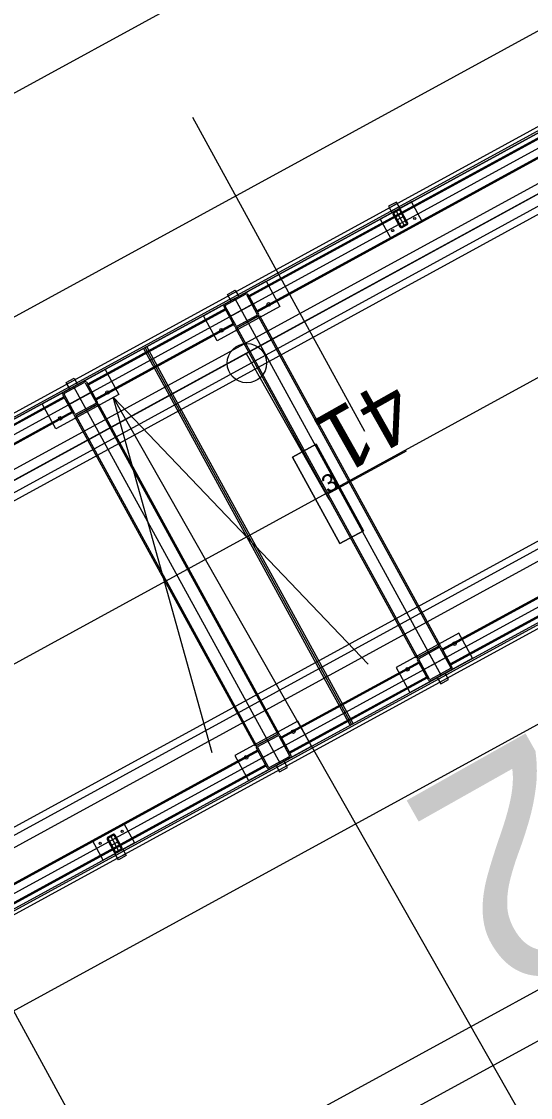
# Model space of a CAD drawing. Extents: x -783978 to -783565, y -1064821 to -1064596.
# Drawn here: x -783770.68 to -783767.84, y -1064687.65 to -1064681.64 of the extents above; entities that cross this region are included whole.
import ezdxf

# ---------------------------------------------------------------- set-up
doc = ezdxf.new("R2010")
doc.units = 0
for name, color, linetype in [('Default', 7, 'Continuous'), ('SO 01_11_01', 7, 'Continuous'), ('SO 01_20_01', 7, 'Continuous'), ('SO 01_50_01', 7, 'Continuous'), ('SO 01_74_01', 7, 'Continuous'), ('SO 01_86_02', 7, 'Continuous'), ('SO 01_86_04', 7, 'Continuous')]:
    doc.layers.add(name, color=color, linetype=linetype)

# ---------------------------------------------------------------- blocks, each defined once
blk = doc.blocks.new('POINT_DISPLAY')
at = {"layer": 'Default'}
blk.add_line((0, 0), (0, 0), dxfattribs=at)

msp = doc.modelspace()

# ---------------------------------------------------------------- linework, layer by layer
at = {"layer": 'SO 01_11_01'}
for p, q in [((-783772.8819, -1064683.2217), (-783730.898, -1064660.279)), ((-783768.6111, -1064691.0302), (-783772.8819, -1064683.2217)), ((-783767.2032, -1064688.9576), (-783770.1671, -1064683.7408))]:
    msp.add_line(p, q, dxfattribs=at)
msp.add_lwpolyline([(-783769.6139, -1064685.7267), (-783770.1671, -1064683.7408), (-783768.7444, -1064685.2327)], dxfattribs=at)
at = {"layer": 'SO 01_20_01'}
for p, q in [((-783735.0054, -1064663.7532), (-783787.4671, -1064692.4555)), ((-783735.2041, -1064664.4318), (-783786.7885, -1064692.6541)), ((-783786.6445, -1064692.9173), (-783735.3233, -1064664.839)), ((-783738.0171, -1064666.3812), (-783786.4402, -1064692.874)), ((-783786.421, -1064692.9091), (-783737.9979, -1064666.4163)), ((-783737.8741, -1064667.2605), (-783785.3352, -1064693.2269)), ((-783737.0912, -1064667.858), (-783785.7805, -1064694.4964)), ((-783785.6531, -1064694.3127), (-783737.23, -1064667.82)), ((-783737.2108, -1064667.855), (-783785.6339, -1064694.3478)), ((-783785.6366, -1064694.7596), (-783736.9472, -1064668.1212)), ((-783746.2961, -1064673.8055), (-783785.8354, -1064695.4379)), ((-783769.8533, -1064683.7307), (-783769.9973, -1064683.4675)), ((-783768.8366, -1064685.5682), (-783769.9885, -1064683.4627)), ((-783769.8357, -1064683.7211), (-783769.9797, -1064683.4579)), ((-783768.9893, -1064685.3098), (-783769.8533, -1064683.7307)), ((-783768.9718, -1064685.3002), (-783769.8357, -1064683.7211)), ((-783768.8453, -1064685.573), (-783768.9893, -1064685.3098)), ((-783768.8278, -1064685.5634), (-783768.9718, -1064685.3002))]:
    msp.add_line(p, q, dxfattribs=at)
at = {"layer": 'SO 01_50_01'}
for p, q in [((-783786.7885, -1064692.6541), (-783725.4827, -1064659.1131)), ((-783769.2428, -1064683.0547), (-783764.8564, -1064680.6549)), ((-783769.2427, -1064683.0548), (-783764.8563, -1064680.655)), ((-783769.2427, -1064683.0548), (-783764.8563, -1064680.655)), ((-783768.7628, -1064683.932), (-783769.7228, -1064682.1774)), ((-783773.6292, -1064685.4546), (-783769.2428, -1064683.0547)), ((-783773.6292, -1064685.4547), (-783769.2427, -1064683.0548)), ((-783773.6292, -1064685.4547), (-783769.2427, -1064683.0548))]:
    msp.add_line(p, q, dxfattribs=at)
for points in [[(-783784.7751, -1064696.3401), (-783745.2333, -1064674.7064)], [(-783784.6553, -1064696.5595), (-783745.1133, -1064674.9257)]]:
    msp.add_lwpolyline(points, dxfattribs=at)
at = {"layer": 'SO 01_74_01'}
for p, q in [((-783735.2185, -1064664.4055), (-783786.6099, -1064692.5222)), ((-783786.6003, -1064692.5398), (-783735.2089, -1064664.423)), ((-783785.4388, -1064694.6628), (-783745.8293, -1064672.9921)), ((-783745.8197, -1064673.0096), (-783785.4292, -1064694.6803)), ((-783766.8446, -1064681.7711), (-783769.4106, -1064683.175)), ((-783766.8416, -1064681.7767), (-783769.4076, -1064683.1806)), ((-783769.3657, -1064683.2572), (-783766.7996, -1064681.8533)), ((-783769.3626, -1064683.2628), (-783766.7966, -1064681.8589)), ((-783768.5865, -1064682.6501), (-783768.6304, -1064682.6741)), ((-783768.5673, -1064682.6851), (-783768.5865, -1064682.6501)), ((-783768.6304, -1064682.6741), (-783768.6112, -1064682.7091)), ((-783768.5817, -1064682.6588), (-783768.6256, -1064682.6828)), ((-783768.6256, -1064682.6828), (-783768.616, -1064682.7004)), ((-783768.616, -1064682.7004), (-783768.5721, -1064682.6764)), ((-783768.6112, -1064682.7091), (-783768.5673, -1064682.6851)), ((-783768.5721, -1064682.6764), (-783768.5817, -1064682.6588)), ((-783769.5296, -1064683.166), (-783769.4857, -1064683.142)), ((-783769.5104, -1064683.2011), (-783769.5296, -1064683.166)), ((-783769.4665, -1064683.1771), (-783769.5104, -1064683.2011)), ((-783769.4857, -1064683.142), (-783769.4665, -1064683.1771)), ((-783769.4106, -1064683.175), (-783769.3626, -1064683.2628)), ((-783769.4076, -1064683.1806), (-783769.3657, -1064683.2572)), ((-783769.5422, -1064683.247), (-783770.3099, -1064683.667)), ((-783769.5392, -1064683.2526), (-783770.3068, -1064683.6725)), ((-783769.4942, -1064683.3348), (-783769.5422, -1064683.247)), ((-783769.4973, -1064683.3292), (-783769.5392, -1064683.2526)), ((-783769.4822, -1064683.3567), (-783769.3506, -1064683.2847)), ((-783769.4752, -1064683.3529), (-783769.3577, -1064683.2885)), ((-783769.3577, -1064683.2885), (-783768.3497, -1064685.1308)), ((-783769.3506, -1064683.2847), (-783768.3427, -1064685.127)), ((-783770.2649, -1064683.7492), (-783769.4973, -1064683.3292)), ((-783770.2619, -1064683.7547), (-783769.4942, -1064683.3348)), ((-783768.4743, -1064685.199), (-783769.4822, -1064683.3567)), ((-783768.4673, -1064685.1952), (-783769.4752, -1064683.3529)), ((-783770.4288, -1064683.658), (-783770.3849, -1064683.634)), ((-783770.4096, -1064683.6931), (-783770.4288, -1064683.658)), ((-783770.3657, -1064683.6691), (-783770.4096, -1064683.6931)), ((-783770.3849, -1064683.634), (-783770.3657, -1064683.6691)), ((-783770.3099, -1064683.667), (-783770.2619, -1064683.7547)), ((-783770.3068, -1064683.6725), (-783770.2649, -1064683.7492)), ((-783770.4415, -1064683.739), (-783773.0075, -1064685.1429)), ((-783770.4384, -1064683.7445), (-783773.0045, -1064685.1485)), ((-783770.3935, -1064683.8267), (-783770.4415, -1064683.739)), ((-783770.3965, -1064683.8212), (-783770.4384, -1064683.7445)), ((-783770.3815, -1064683.8487), (-783770.2499, -1064683.7767)), ((-783770.3744, -1064683.8448), (-783770.2569, -1064683.7805)), ((-783770.2569, -1064683.7805), (-783769.2489, -1064685.6228)), ((-783770.2499, -1064683.7767), (-783769.2419, -1064685.619)), ((-783765.7646, -1064683.745), (-783768.3307, -1064685.1489)), ((-783765.7616, -1064683.7505), (-783768.3277, -1064685.1545)), ((-783772.9625, -1064685.2251), (-783770.3965, -1064683.8212)), ((-783772.9595, -1064685.2307), (-783770.3935, -1064683.8267)), ((-783769.3735, -1064685.691), (-783770.3815, -1064683.8487)), ((-783769.3665, -1064685.6871), (-783770.3744, -1064683.8448)), ((-783768.2857, -1064685.2311), (-783765.7197, -1064683.8272)), ((-783768.2827, -1064685.2367), (-783765.7167, -1064683.8328)), ((-783768.3427, -1064685.127), (-783768.4743, -1064685.199)), ((-783768.3497, -1064685.1308), (-783768.4673, -1064685.1952)), ((-783768.3307, -1064685.1489), (-783768.2827, -1064685.2367)), ((-783768.3277, -1064685.1545), (-783768.2857, -1064685.2311)), ((-783768.4623, -1064685.2209), (-783769.2299, -1064685.6409)), ((-783768.4593, -1064685.2265), (-783769.2269, -1064685.6464)), ((-783768.4143, -1064685.3087), (-783768.4623, -1064685.2209)), ((-783768.4173, -1064685.3031), (-783768.4593, -1064685.2265)), ((-783768.3146, -1064685.2826), (-783768.3584, -1064685.3066)), ((-783768.2954, -1064685.3177), (-783768.3146, -1064685.2826)), ((-783769.185, -1064685.7231), (-783768.4173, -1064685.3031)), ((-783769.1819, -1064685.7286), (-783768.4143, -1064685.3087)), ((-783768.3584, -1064685.3066), (-783768.3392, -1064685.3417)), ((-783768.3392, -1064685.3417), (-783768.2954, -1064685.3177)), ((-783769.2419, -1064685.619), (-783769.3735, -1064685.691)), ((-783769.2489, -1064685.6228), (-783769.3665, -1064685.6871)), ((-783769.2299, -1064685.6409), (-783769.1819, -1064685.7286)), ((-783769.2269, -1064685.6464), (-783769.185, -1064685.7231)), ((-783769.3615, -1064685.7129), (-783771.9276, -1064687.1168)), ((-783769.3585, -1064685.7184), (-783771.9245, -1064687.1223)), ((-783769.3135, -1064685.8006), (-783769.3615, -1064685.7129)), ((-783769.3165, -1064685.7951), (-783769.3585, -1064685.7184)), ((-783769.2138, -1064685.7746), (-783769.2577, -1064685.7986)), ((-783769.1946, -1064685.8097), (-783769.2138, -1064685.7746)), ((-783771.8826, -1064687.199), (-783769.3165, -1064685.7951)), ((-783771.8796, -1064687.2045), (-783769.3135, -1064685.8006)), ((-783769.2577, -1064685.7986), (-783769.2385, -1064685.8337)), ((-783769.2385, -1064685.8337), (-783769.1946, -1064685.8097)), ((-783770.1569, -1064686.2905), (-783770.113, -1064686.2665)), ((-783770.1377, -1064686.3256), (-783770.1569, -1064686.2905)), ((-783770.1521, -1064686.2993), (-783770.1082, -1064686.2753)), ((-783770.1425, -1064686.3169), (-783770.1521, -1064686.2993)), ((-783770.0986, -1064686.2929), (-783770.1425, -1064686.3169)), ((-783770.0938, -1064686.3016), (-783770.1377, -1064686.3256)), ((-783770.113, -1064686.2665), (-783770.0938, -1064686.3016)), ((-783770.1082, -1064686.2753), (-783770.0986, -1064686.2929))]:
    msp.add_line(p, q, dxfattribs=at)
for points in [[(-783735.1681, -1064664.4976), (-783787.4762, -1064693.1159)], [(-783734.0882, -1064666.4715), (-783786.3963, -1064695.0898)], [(-783768.5756, -1064682.6897), (-783768.6029, -1064682.7046)], [(-783768.5726, -1064682.6952), (-783768.5998, -1064682.7101)], [(-783768.5892, -1064682.6971), (-783768.5412, -1064682.7849)], [(-783768.5294, -1064682.7676), (-783768.5683, -1064682.6965)], [(-783768.5238, -1064682.7646), (-783768.5628, -1064682.6934)], [(-783768.6066, -1064682.7174), (-783768.5677, -1064682.7886)], [(-783768.6011, -1064682.7144), (-783768.5622, -1064682.7856)], [(-783768.5433, -1064682.729), (-783768.5872, -1064682.753)], [(-783768.5579, -1064682.7868), (-783768.5306, -1064682.7719)], [(-783768.5549, -1064682.7923), (-783768.5276, -1064682.7774)], [(-783769.5437, -1064683.2194), (-783769.4332, -1064683.1589)], [(-783769.5399, -1064683.2264), (-783769.4293, -1064683.1659)], [(-783769.4884, -1064683.1891), (-783768.3365, -1064685.2946)], [(-783769.4884, -1064683.1891), (-783769.4164, -1064683.3207)], [(-783769.4239, -1064683.1675), (-783769.3634, -1064683.278)], [(-783769.4169, -1064683.1636), (-783769.3564, -1064683.2742)], [(-783769.488, -1064683.3462), (-783769.5485, -1064683.2356)], [(-783769.481, -1064683.3423), (-783769.5415, -1064683.2318)], [(-783769.3866, -1064683.2189), (-783769.5182, -1064683.2909)], [(-783769.365, -1064683.2834), (-783769.4755, -1064683.3439)], [(-783769.3612, -1064683.2905), (-783769.4717, -1064683.3509)], [(-783770.4429, -1064683.7113), (-783770.3324, -1064683.6508)], [(-783770.4391, -1064683.7183), (-783770.3285, -1064683.6579)], [(-783770.3231, -1064683.6595), (-783770.2626, -1064683.77)], [(-783770.3161, -1064683.6556), (-783770.2556, -1064683.7662)], [(-783770.3872, -1064683.8381), (-783770.4477, -1064683.7276)], [(-783770.3802, -1064683.8343), (-783770.4407, -1064683.7238)], [(-783770.2859, -1064683.7109), (-783770.4175, -1064683.7829)], [(-783770.3877, -1064683.6811), (-783769.2357, -1064685.7866)], [(-783770.3877, -1064683.6811), (-783770.3157, -1064683.8127)], [(-783770.2642, -1064683.7754), (-783770.3748, -1064683.8359)], [(-783770.2604, -1064683.7824), (-783770.3709, -1064683.8429)], [(-783768.4638, -1064685.1932), (-783768.3532, -1064685.1328)], [(-783768.4599, -1064685.2003), (-783768.3494, -1064685.1398)], [(-783768.4085, -1064685.163), (-783768.3365, -1064685.2946)], [(-783768.344, -1064685.1414), (-783768.2835, -1064685.2519)], [(-783768.3369, -1064685.1375), (-783768.2765, -1064685.2481)], [(-783768.4081, -1064685.3201), (-783768.4685, -1064685.2095)], [(-783768.401, -1064685.3162), (-783768.4615, -1064685.2057)], [(-783768.3067, -1064685.1928), (-783768.4383, -1064685.2648)], [(-783768.2851, -1064685.2573), (-783768.3956, -1064685.3178)], [(-783768.2812, -1064685.2644), (-783768.3918, -1064685.3248)], [(-783769.363, -1064685.6852), (-783769.2525, -1064685.6247)], [(-783769.3591, -1064685.6922), (-783769.2486, -1064685.6318)], [(-783769.3077, -1064685.655), (-783769.2357, -1064685.7866)], [(-783769.2432, -1064685.6333), (-783769.1827, -1064685.7439)], [(-783769.2362, -1064685.6295), (-783769.1757, -1064685.74)], [(-783769.3073, -1064685.812), (-783769.3678, -1064685.7015)], [(-783769.3003, -1064685.8082), (-783769.3607, -1064685.6977)], [(-783769.2059, -1064685.6848), (-783769.3375, -1064685.7568)], [(-783769.1843, -1064685.7493), (-783769.2948, -1064685.8098)], [(-783769.1805, -1064685.7563), (-783769.291, -1064685.8168)], [(-783770.1693, -1064686.1833), (-783770.1966, -1064686.1983)], [(-783770.1663, -1064686.1889), (-783770.1936, -1064686.2038)], [(-783770.1829, -1064686.1908), (-783770.1349, -1064686.2785)], [(-783770.1231, -1064686.2613), (-783770.162, -1064686.1901)], [(-783770.1175, -1064686.2582), (-783770.1565, -1064686.1871)], [(-783770.2003, -1064686.2111), (-783770.1614, -1064686.2822)], [(-783770.1948, -1064686.2081), (-783770.1559, -1064686.2792)], [(-783770.137, -1064686.2227), (-783770.1809, -1064686.2467)], [(-783770.1516, -1064686.2805), (-783770.1243, -1064686.2655)], [(-783770.1486, -1064686.286), (-783770.1213, -1064686.2711)]]:
    msp.add_lwpolyline(points, dxfattribs=at)
for points in [[(-783768.5015, -1064682.6491), (-783768.6769, -1064682.7451), (-783768.6194, -1064682.8504), (-783768.4439, -1064682.7544)], [(-783769.2362, -1064683.2335), (-783769.5871, -1064683.4255), (-783769.6639, -1064683.2851), (-783769.313, -1064683.0931)], [(-783770.1354, -1064683.7255), (-783770.4863, -1064683.9174), (-783770.5631, -1064683.7771), (-783770.2122, -1064683.5851)], [(-783768.2378, -1064685.0582), (-783768.5888, -1064685.2502), (-783768.512, -1064685.3906), (-783768.161, -1064685.1986)], [(-783769.1371, -1064685.5502), (-783769.488, -1064685.7422), (-783769.4112, -1064685.8826), (-783769.0603, -1064685.6906)], [(-783770.0472, -1064686.2305), (-783770.2227, -1064686.3265), (-783770.2803, -1064686.2213), (-783770.1048, -1064686.1253)]]:
    msp.add_lwpolyline(points, close=True, dxfattribs=at)
for centre, radius in [((-783768.4846, -1064682.7425), 0.006), ((-783768.6074, -1064682.8097), 0.006), ((-783769.2992, -1064683.2224), 0.01), ((-783769.5624, -1064683.3664), 0.01), ((-783770.1985, -1064683.7144), 0.01), ((-783770.4616, -1064683.8584), 0.01), ((-783768.2625, -1064685.1173), 0.01), ((-783768.5257, -1064685.2613), 0.01), ((-783769.1617, -1064685.6093), 0.01), ((-783769.4249, -1064685.7533), 0.01), ((-783770.1167, -1064686.166), 0.006), ((-783770.2395, -1064686.2332), 0.006)]:
    msp.add_circle(centre, radius, dxfattribs=at)
for centre, radius, start, end in [((-783768.5983, -1064682.7129), 0.00945, 118.68349, 208.68349), ((-783768.5983, -1064682.7129), 0.00315, 118.68349, 208.68349), ((-783768.571, -1064682.698), 0.00945, 28.68349, 118.68349), ((-783768.571, -1064682.698), 0.00315, 28.68349, 118.68349), ((-783768.5321, -1064682.7691), 0.00315, 298.68349, 28.68349), ((-783768.5321, -1064682.7691), 0.00945, 298.68349, 28.68349), ((-783768.5594, -1064682.784), 0.00945, 208.68349, 298.68349), ((-783768.5594, -1064682.784), 0.00315, 208.68349, 298.68349), ((-783769.4274, -1064683.1694), 0.012, 28.68349, 118.68349), ((-783769.4274, -1064683.1694), 0.004, 28.68349, 118.68349), ((-783769.5379, -1064683.2299), 0.012, 118.68349, 208.68349), ((-783769.5379, -1064683.2299), 0.004, 118.68349, 208.68349), ((-783769.3669, -1064683.2799), 0.004, 298.68349, 28.68349), ((-783769.3669, -1064683.2799), 0.012, 298.68349, 28.68349), ((-783769.4775, -1064683.3404), 0.012, 208.68349, 298.68349), ((-783769.4775, -1064683.3404), 0.004, 208.68349, 298.68349), ((-783770.3266, -1064683.6614), 0.012, 28.68349, 118.68349), ((-783770.3266, -1064683.6614), 0.004, 28.68349, 118.68349), ((-783770.4372, -1064683.7218), 0.012, 118.68349, 208.68349), ((-783770.4372, -1064683.7218), 0.004, 118.68349, 208.68349), ((-783770.2661, -1064683.7719), 0.004, 298.68349, 28.68349), ((-783770.2661, -1064683.7719), 0.012, 298.68349, 28.68349), ((-783770.3767, -1064683.8324), 0.012, 208.68349, 298.68349), ((-783770.3767, -1064683.8324), 0.004, 208.68349, 298.68349), ((-783768.3475, -1064685.1433), 0.012, 28.68349, 118.68349), ((-783768.3475, -1064685.1433), 0.004, 28.68349, 118.68349), ((-783768.458, -1064685.2038), 0.012, 118.68349, 208.68349), ((-783768.458, -1064685.2038), 0.004, 118.68349, 208.68349), ((-783768.287, -1064685.2538), 0.004, 298.68349, 28.68349), ((-783768.287, -1064685.2538), 0.012, 298.68349, 28.68349), ((-783768.3975, -1064685.3143), 0.012, 208.68349, 298.68349), ((-783768.3975, -1064685.3143), 0.004, 208.68349, 298.68349), ((-783769.2467, -1064685.6353), 0.012, 28.68349, 118.68349), ((-783769.2467, -1064685.6353), 0.004, 28.68349, 118.68349), ((-783769.3572, -1064685.6957), 0.012, 118.68349, 208.68349), ((-783769.3572, -1064685.6957), 0.004, 118.68349, 208.68349), ((-783769.1862, -1064685.7458), 0.004, 298.68349, 28.68349), ((-783769.1862, -1064685.7458), 0.012, 298.68349, 28.68349), ((-783769.2968, -1064685.8063), 0.012, 208.68349, 298.68349), ((-783769.2968, -1064685.8063), 0.004, 208.68349, 298.68349), ((-783770.192, -1064686.2066), 0.00945, 118.68349, 208.68349), ((-783770.1648, -1064686.1916), 0.00945, 28.68349, 118.68349), ((-783770.1648, -1064686.1916), 0.00315, 28.68349, 118.68349), ((-783770.192, -1064686.2066), 0.00315, 118.68349, 208.68349), ((-783770.1258, -1064686.2628), 0.00945, 298.68349, 28.68349), ((-783770.1531, -1064686.2777), 0.00945, 208.68349, 298.68349), ((-783770.1531, -1064686.2777), 0.00315, 208.68349, 298.68349), ((-783770.1258, -1064686.2628), 0.00315, 298.68349, 28.68349)]:
    msp.add_arc(centre, radius, start, end, dxfattribs=at)
at = {"layer": 'SO 01_86_04'}
for p, q in [((-783769.4242, -1064683.4959), (-783768.9641, -1064684.3106)), ((-783769.0347, -1064684.0039), (-783769.1663, -1064684.0759)), ((-783769.0347, -1064684.0039), (-783769.1663, -1064684.0759)), ((-783769.1663, -1064684.0759), (-783769.0347, -1064684.0039)), ((-783769.1663, -1064684.0759), (-783769.0347, -1064684.0039)), ((-783768.7707, -1064684.4864), (-783769.0347, -1064684.0039)), ((-783768.7707, -1064684.4864), (-783769.0347, -1064684.0039)), ((-783769.0347, -1064684.0039), (-783768.7707, -1064684.4864)), ((-783769.0347, -1064684.0039), (-783768.7707, -1064684.4864)), ((-783769.1663, -1064684.0759), (-783768.9023, -1064684.5584)), ((-783769.1663, -1064684.0759), (-783768.9023, -1064684.5584)), ((-783768.9023, -1064684.5584), (-783769.1663, -1064684.0759)), ((-783768.9023, -1064684.5584), (-783769.1663, -1064684.0759)), ((-783768.9685, -1064684.2811), (-783768.5298, -1064684.0411)), ((-783768.9023, -1064684.5584), (-783768.7707, -1064684.4864)), ((-783768.9023, -1064684.5584), (-783768.7707, -1064684.4864)), ((-783768.7707, -1064684.4864), (-783768.9023, -1064684.5584)), ((-783768.7707, -1064684.4864), (-783768.9023, -1064684.5584))]:
    msp.add_line(p, q, dxfattribs=at)
for points in [[(-783738.3222, -1064666.4797), (-783740.5325, -1064667.689), (-783743.1715, -1064669.1328), (-783745.7538, -1064670.5456), (-783748.4385, -1064672.0145), (-783751.0413, -1064673.4385), (-783753.6847, -1064674.8847), (-783756.3281, -1064676.3309), (-783758.9715, -1064677.7772), (-783761.6149, -1064679.2234), (-783764.2583, -1064680.6696), (-783766.9018, -1064682.1159), (-783769.4633, -1064683.5173), (-783772.109, -1064684.9648), (-783774.7882, -1064686.4306), (-783778.1382, -1064688.2722), (-783783.8139, -1064691.3971), (-783785.747, -1064692.4898)], [(-783747.063, -1064670.9765), (-783746.9575, -1064671.1681), (-783786.6893, -1064692.8619), (-783786.185, -1064693.7636)]]:
    msp.add_lwpolyline(points, dxfattribs=at)
msp.add_circle((-783769.4208, -1064683.5503), 0.1097, dxfattribs=at)

# ---------------------------------------------------------------- block references
at = {"layer": 'SO 01_86_04', "xscale": 0.010000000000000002, "yscale": 0.009999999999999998, "rotation": 28.683491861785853}
for p in [(-783769.0347, -1064684.0039), (-783769.0347, -1064684.0039), (-783769.1663, -1064684.0759), (-783769.1663, -1064684.0759), (-783768.7707, -1064684.4864), (-783768.7707, -1064684.4864), (-783768.9023, -1064684.5584), (-783768.9023, -1064684.5584)]:
    msp.add_blockref('POINT_DISPLAY', p, dxfattribs=at)

# ---------------------------------------------------------------- texts
at = {"layer": 'SO 01_86_02'}
msp.add_text('OS2', height=1.25, rotation=209.44605, dxfattribs=at).set_placement((-783765.6897, -1064684.3906))
at = {"layer": 'SO 01_86_04'}
for s, height, rotation, p in [('41', 0.351, 209.46001, (-783768.6118, -1064683.6214)), ('3', 0.1, 28.68349, (-783768.9685, -1064684.2811))]:
    msp.add_text(s, height=height, rotation=rotation, dxfattribs=at).set_placement(p)

doc.saveas('drawing.dxf')
